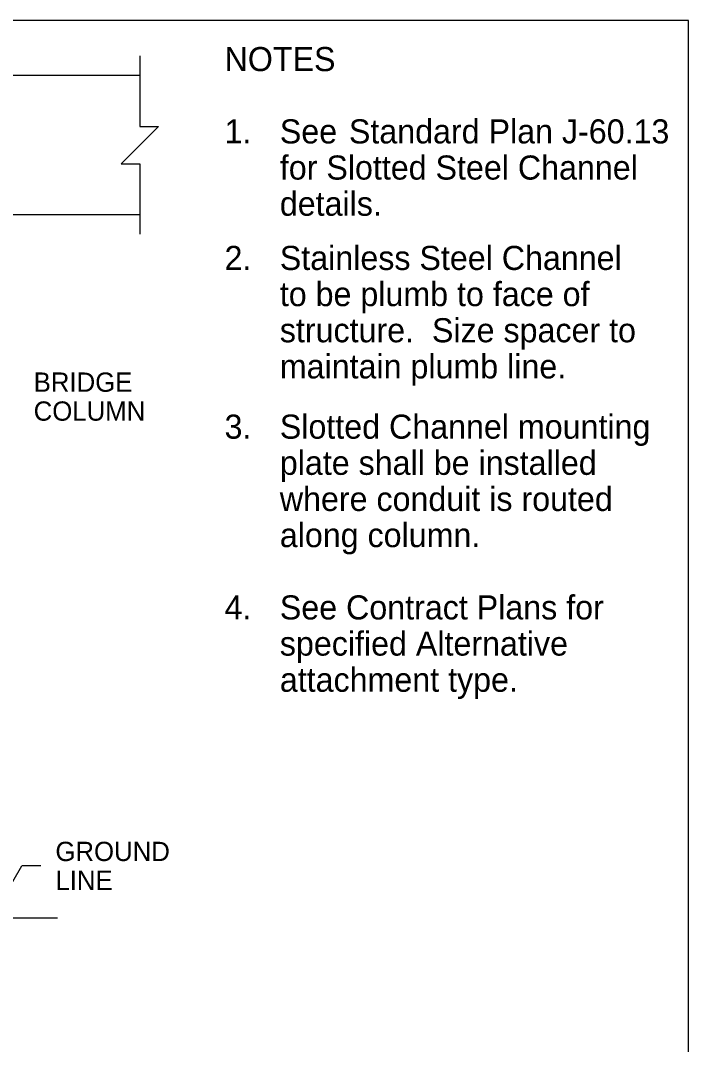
# Model space of a CAD drawing. Extents: x 99862 to 103680, y 99470 to 102076.
# Drawn here: x 102596 to 103151, y 101226 to 102076 of the extents above; entities that cross this region are included whole.
import ezdxf

# ---------------------------------------------------------------- set-up
doc = ezdxf.new("R2010")
doc.units = 0
for name, color, linetype in [('Level 1', 7, 'Continuous'), ('Level 10', 7, 'Continuous'), ('Level 12', 7, 'Continuous'), ('Level 15', 7, 'Continuous'), ('Level 20', 7, 'Continuous'), ('Level 60', 7, 'Continuous')]:
    doc.layers.add(name, color=color, linetype=linetype)

msp = doc.modelspace()

# ---------------------------------------------------------------- linework, layer by layer
at = {"layer": 'Level 1'}
msp.add_lwpolyline([(99862, 99999.5), (103151, 99999.5), (103151, 102075.5), (99862, 102075.5)], close=True, dxfattribs=at)
at = {"layer": 'Level 10'}
for p, q in [((102075.16, 102030.05), (102695.22, 102030.05)), ((102695.22, 101914.19), (102075.16, 101914.19))]:
    msp.add_line(p, q, dxfattribs=at)
at = {"layer": 'Level 12'}
msp.add_line((102163.59, 101330.84), (102626.91, 101330.84), dxfattribs=at)
at = {"layer": 'Level 15'}
for p in [(102572.19, 101330.84), (102613.11, 101374)]:
    msp.add_line(p, (102597.11, 101374), dxfattribs=at)
msp.add_lwpolyline([(102695.22, 102046.05), (102695.22, 101987.61), (102710.71, 101987.61), (102679.74, 101956.63), (102695.22, 101956.63), (102695.22, 101898.19)], dxfattribs=at)
at = {"layer": 'Level 60'}
msp.add_line((103151, 102075.5), (103151, 102075.5), dxfattribs=at)

# ---------------------------------------------------------------- texts
at = {"layer": 'Level 20'}
for s, height, p in [('NOTES', 20, (102765.62, 102033.47)), ('Standard Plan J-60.13 ', 20, (102868.91, 101973.47)), ('1.', 20, (102765.62, 101973.47)), ('See ', 20, (102811.53, 101973.47)), ('for Slotted Steel Channel ', 20, (102811.53, 101943.47)), ('details.', 20, (102811.53, 101913.47)), ('2.', 20, (102765.62, 101868.47)), ('Stainless Steel Channel ', 20, (102811.53, 101868.47)), ('to be plumb to face of ', 20, (102811.53, 101838.47)), ('structure.  Size spacer to ', 20, (102811.53, 101808.47)), ('maintain plumb line.  ', 20, (102811.53, 101778.47)), ('BRIDGE', 16, (102607.06, 101767.4)), ('COLUMN', 16, (102607.06, 101743.4)), ('3.', 20, (102765.62, 101728.47)), ('Slotted Channel mounting ', 20, (102811.53, 101728.47)), ('plate shall be installed ', 20, (102811.53, 101698.47)), ('where conduit is routed ', 20, (102811.53, 101668.47)), ('along column.', 20, (102811.53, 101638.47)), ('4.', 20, (102765.62, 101578.47)), ('See Contract Plans for', 20, (102811.53, 101578.47)), ('specified Alternative', 20, (102811.53, 101548.47)), ('attachment type.', 20, (102811.53, 101518.47))]:
    msp.add_text(s, height=height, dxfattribs=at).set_placement(p)
for s, p in [('GROUND', (102625.11, 101378)), ('LINE', (102625.11, 101354))]:
    msp.add_text(s, height=16, rotation=360, dxfattribs=at).set_placement(p)

doc.saveas('drawing.dxf')
